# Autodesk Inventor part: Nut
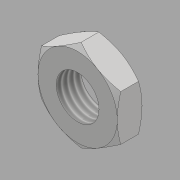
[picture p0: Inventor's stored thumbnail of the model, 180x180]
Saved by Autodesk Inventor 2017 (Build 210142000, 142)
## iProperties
Created: 2016-05
Part Number: Nut
Material: Generic
Document SubType Name: Modeling
Designer: CADCIM
Density: 1 g/cm^3
Appearance: Default
Author: CADCIM
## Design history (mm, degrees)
sketch "Sketch1"
  geometry: L1 (9.6, -5.543)-(0, -11.085); L2 (0, -11.085)-(-9.6, -5.543); L3 (-9.6, -5.543)-(-9.6, 5.543); L4 (-9.6, 5.543)-(0, 11.085); L5 (0, 11.085)-(9.6, 5.543); L6 (9.6, 5.543)-(9.6, -5.543); 2 further points
  constraints: 12 end point, 1 coincident, 1 vertical alignment, 13 other
  dimensions: "d0" = 19.2 distance between parallel lines of L3 L6
extrude "Extrusion1" new body sketch "Sketch1" distance "d1" = 6; taper "d2" = 0 deg
sketch "Sketch2"
  geometry: L1 (0, 11.085)-(-9.6, 5.543) reference; C1 r 9.6 at (0, 0); 1 further point
  constraints: 1 centre point, 1 coincident, 1 tangent
extrude "Extrusion2" sketch "Sketch2" distance "d3" = 10.8; taper "d4" = 60 deg
workplane "Work Plane1"
sketch "Sketch3"
  geometry: L1 (0, -11.085)-(9.6, -5.543) reference; C1 r 9.6 at (0, 0); 1 further point
  constraints: 1 centre point, 1 coincident, 1 tangent
extrude "Extrusion3" sketch "Sketch3" distance "d5" = 10.8; taper "d6" = 60 deg
sketch "Sketch4"
  geometry: 1 further point
hole "Hole1" diameter "d9" = 10.376; stored, may be unused: countersink angle "d13" = 90 deg, drill point angle "d15" = 118 deg; dims "d7" = 10, "d8" = 10, "d10" = 24, "d11" = 4, "d12" = 2, "d14" = 31.3
body "Solid1"
